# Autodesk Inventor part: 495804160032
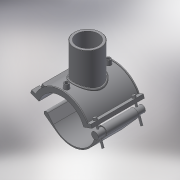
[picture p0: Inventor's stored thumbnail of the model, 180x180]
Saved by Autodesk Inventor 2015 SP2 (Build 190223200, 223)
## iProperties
Created: 2017-07
Part Number: 495804160032
Material: Generic
Description: PLASSON BRANCH SADDLE 160-32
Document SubType Name: Modeling
Designer: KIM
Density: 1 g/cm^3
Appearance: Default
Author: KIM
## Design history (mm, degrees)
derived "495804.ipt"
feature "Solid1::495804.ipt"
feature "Solid2::495804.ipt"
tag "TaggingFeature1"
body "Solid1"
body "Solid2"
other parameters: "d4" = 118, "d5" = 0, "d6" = 0.1, "d8" = 0, "d19" = 6, "d20" = 6, "d21" = 70.8, "d23" = 0, "d24" = 35.4, "d26" = 0, "d27" = 3, "d28" = 3, "d29" = 3, "d30" = 53.33333, "d31" = 6, "d32" = 0, "d33" = 0, "d34" = 0.6, "d40" = 93.6, "d41" = 35.2, "d43" = 0, "d45" = 0, "d47" = 149, "d48" = 32, "d50" = 0, "d70" = 15, "d72" = 0, "d73" = 6, "d75" = 5, "d76" = 0, "d77" = 8, "d79" = 15, "d80" = 47.2, "d82" = 5 deg, "d84" = 4, "d85" = 14, "d86" = 0, "d87" = 3, "d88" = 0, "d89" = 1, "d90" = 1, "d91" = 94.4, "d92" = 0, "d93" = 0.5, "d94" = 84.21053, "d96" = 183.6, "d97" = 2.36, "d98" = 0, "d102" = 0.96, "d103" = 25.6, "d105" = 0, "d109" = -19.66667, "d117" = 0.32, "d120" = 140 deg, "d121" = 24.228, "d122" = 20 deg, "d124" = 108, "d126" = 0, "d143" = 168, "d150" = 28.8, "d159" = 4, "d161" = 4, "d162" = 70.8, "d163" = 0, "d167" = 32, "d168" = 81.81818, "d173" = 1, "d176" = 20 deg, "d177" = 11.2, "d180" = 0, "d185" = 38.35, "d186" = 38.35, "d188" = 6, "d189" = 11.2, "d190" = 0, "d191" = 135, "d202" = 0, "d216" = 106.2, "d217" = 0, "d221" = 43.66, "d222" = 11.2, "d223" = 6.72, "d225" = 6.72, "d227" = 23.04, "d230" = 99.2, "d236" = 20 deg, "d237" = 97, "d238" = 20 deg, "d239" = 11.2, "H_" = 59, "L_" = 118, "d_t" = 6, "d_1" = 32, "H_1" = 49, "d148" = 4, "d160" = 4
